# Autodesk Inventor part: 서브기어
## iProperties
Company: 한국ATC센터
Created: 2014-12
Part Number: 서브기어
Document SubType Name: Modeling
Designer: KYOUNG IL JANG
Density: 1 g/cm^3
Mass: 15.166 g
Surface Area: 69.6172 cm^2
Volume: 15.166 cm^3
Author: KYOUNG IL JANG
